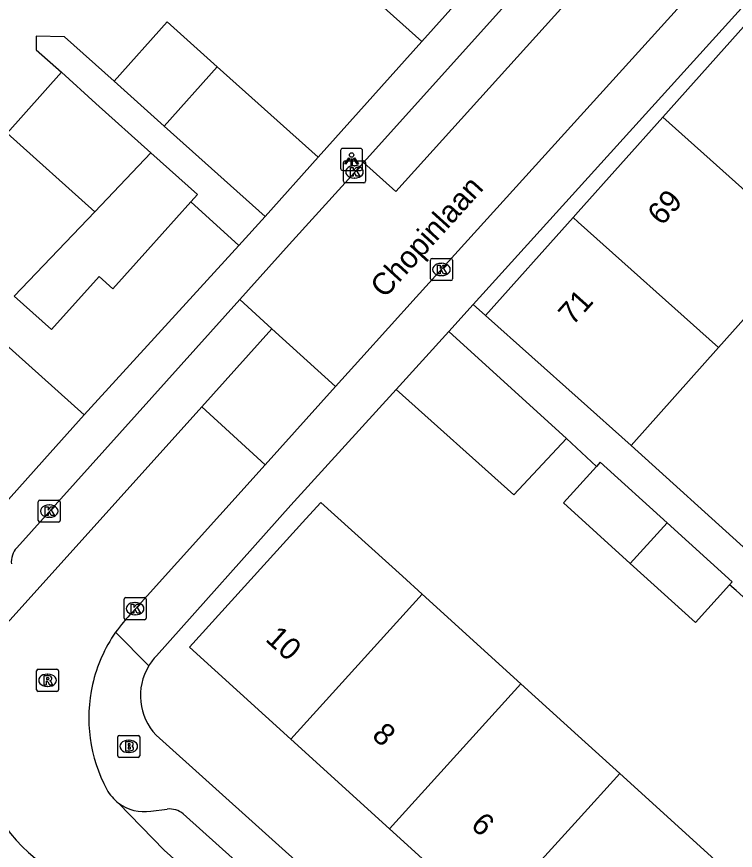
# Model space of a CAD drawing. Extents: x 159040 to 160094, y 381214 to 382518.
# Drawn here: x 159474.48 to 159507.14, y 381732.23 to 381770.11 of the extents above; entities that cross this region are included whole.
import ezdxf

# ---------------------------------------------------------------- set-up
doc = ezdxf.new("R2010")
doc.units = 0
for name, color, linetype in [('IMGEO_Brandkraan', 7, 'Continuous'), ('IMGEO_Kolk', 7, 'Continuous'), ('IMGEO_Lichtpunt', 7, 'Continuous'), ('IMGEO_Muur', 7, 'Continuous'), ('IMGEO_Openbare_ruimte_label', 7, 'Continuous'), ('IMGEO_Pand', 7, 'Continuous'), ('IMGEO_Pand_nummerreeks', 7, 'Continuous'), ('IMGEO_Parkeervlak_open', 7, 'Continuous'), ('IMGEO_Rijbaan_lokaal_open', 7, 'Continuous'), ('IMGEO_Rioolput', 7, 'Continuous'), ('IMGEO_Voetpad_open', 7, 'Continuous')]:
    doc.layers.add(name, color=color, linetype=linetype)

msp = doc.modelspace()

# ---------------------------------------------------------------- linework, layer by layer
at = {"layer": 'IMGEO_Brandkraan'}
for p, q in [((159479.08, 381736.53), (159479.08, 381737.382)), ((159479.155, 381737.456), (159480.007, 381737.456)), ((159480.081, 381737.382), (159480.081, 381736.53)), ((159479.568, 381737.236), (159479.593, 381737.236)), ((159479.591, 381736.676), (159479.566, 381736.676)), ((159480.007, 381736.456), (159479.155, 381736.456))]:
    msp.add_line(p, q, dxfattribs=at)
for points in [[(159479.08, 381736.53), (159479.08, 381737.382)], [(159479.155, 381737.456), (159480.007, 381737.456)], [(159480.081, 381737.382), (159480.081, 381736.53)], [(159479.428, 381737.156), (159479.428, 381736.756), (159479.641, 381736.756)], [(159479.659, 381737.156), (159479.428, 381737.156)], [(159479.607, 381737.075), (159479.553, 381737.075), (159479.553, 381736.999)], [(159479.553, 381736.999), (159479.606, 381736.999)], [(159479.615, 381736.923), (159479.553, 381736.923), (159479.553, 381736.842)], [(159479.553, 381736.842), (159479.615, 381736.842)], [(159480.007, 381736.456), (159479.155, 381736.456)]]:
    msp.add_lwpolyline(points, dxfattribs=at)
for centre, radius, start, end in [((159479.157, 381737.38), 0.0765, 91.552, 178.448), ((159479.157, 381737.38), 0.0765, 91.552, 178.448), ((159480.005, 381737.38), 0.0765, 1.552, 88.448), ((159480.005, 381737.38), 0.0765, 1.552, 88.448), ((159479.608, 381737.037), 0.0379, 267.8285, 90.9355), ((159479.663, 381737.011), 0.145, 59.4692, 91.5367), ((159479.688, 381737.058), 0.0922, 285.5137, 58.1501), ((159479.693, 381736.866), 0.105, 301.3115, 78.989), ((159479.616, 381736.882), 0.0404, 269.8759, 90.5077), ((159479.647, 381737.007), 0.251, 268.6676, 293.5347), ((159479.157, 381736.532), 0.0765, 181.552, 268.448), ((159479.157, 381736.532), 0.0765, 181.552, 268.448), ((159480.005, 381736.532), 0.0765, 271.552, 358.448), ((159480.005, 381736.532), 0.0765, 271.552, 358.448)]:
    msp.add_arc(centre, radius, start, end, dxfattribs=at)
for centre, major_axis, ratio, start_param, end_param in [((159479.567, 381736.956), (-0.387, 0.002), 0.722429, 4.712389, 7.853982), ((159479.592, 381736.956), (-0.39, 0.002), 0.717154, 1.570796, 4.712389)]:
    msp.add_ellipse(centre, major_axis=major_axis, ratio=ratio, start_param=start_param, end_param=end_param, dxfattribs=at)
at = {"layer": 'IMGEO_Kolk'}
for p, q in [((159489.336, 381762.629), (159489.336, 381763.481)), ((159489.411, 381763.555), (159490.263, 381763.555)), ((159490.337, 381763.481), (159490.337, 381762.629)), ((159489.824, 381763.335), (159489.849, 381763.335)), ((159489.847, 381762.775), (159489.822, 381762.775)), ((159490.263, 381762.555), (159489.411, 381762.555)), ((159493.289, 381758.196), (159493.289, 381759.048)), ((159493.364, 381759.122), (159494.216, 381759.122)), ((159494.29, 381759.048), (159494.29, 381758.196)), ((159493.777, 381758.902), (159493.802, 381758.902)), ((159493.8, 381758.342), (159493.775, 381758.342)), ((159494.216, 381758.122), (159493.364, 381758.122)), ((159475.466, 381747.217), (159475.466, 381748.069)), ((159475.541, 381748.143), (159476.393, 381748.143)), ((159475.954, 381747.923), (159475.979, 381747.923)), ((159476.467, 381748.069), (159476.467, 381747.217)), ((159475.977, 381747.363), (159475.952, 381747.363)), ((159476.393, 381747.143), (159475.541, 381747.143)), ((159479.368, 381742.786), (159479.368, 381743.638)), ((159479.443, 381743.712), (159480.295, 381743.712)), ((159479.856, 381743.492), (159479.881, 381743.492)), ((159480.369, 381743.638), (159480.369, 381742.786)), ((159480.295, 381742.712), (159479.443, 381742.712)), ((159479.879, 381742.932), (159479.854, 381742.932))]:
    msp.add_line(p, q, dxfattribs=at)
for points in [[(159489.336, 381762.629), (159489.336, 381763.481)], [(159489.411, 381763.555), (159490.263, 381763.555)], [(159490.337, 381763.481), (159490.337, 381762.629)], [(159489.657, 381763.255), (159489.78, 381763.255), (159489.78, 381763.104), (159489.91, 381763.255), (159490.074, 381763.255), (159489.928, 381763.104), (159490.081, 381762.855), (159489.929, 381762.855), (159489.844, 381763.019), (159489.78, 381762.952), (159489.78, 381762.855), (159489.657, 381762.855), (159489.657, 381763.255)], [(159490.263, 381762.555), (159489.411, 381762.555)], [(159493.289, 381758.196), (159493.289, 381759.048)], [(159493.364, 381759.122), (159494.216, 381759.122)], [(159494.29, 381759.048), (159494.29, 381758.196)], [(159493.61, 381758.822), (159493.733, 381758.822), (159493.733, 381758.671), (159493.863, 381758.822), (159494.027, 381758.822), (159493.881, 381758.671), (159494.034, 381758.422), (159493.882, 381758.422), (159493.797, 381758.586), (159493.733, 381758.519), (159493.733, 381758.422), (159493.61, 381758.422), (159493.61, 381758.822)], [(159494.216, 381758.122), (159493.364, 381758.122)], [(159475.466, 381747.217), (159475.466, 381748.069)], [(159475.541, 381748.143), (159476.393, 381748.143)], [(159476.467, 381748.069), (159476.467, 381747.217)], [(159475.787, 381747.843), (159475.91, 381747.843), (159475.91, 381747.692), (159476.04, 381747.843), (159476.204, 381747.843), (159476.058, 381747.692), (159476.211, 381747.443), (159476.059, 381747.443), (159475.974, 381747.607), (159475.91, 381747.54), (159475.91, 381747.443), (159475.787, 381747.443), (159475.787, 381747.843)], [(159476.393, 381747.143), (159475.541, 381747.143)], [(159479.368, 381742.786), (159479.368, 381743.638)], [(159479.443, 381743.712), (159480.295, 381743.712)], [(159479.689, 381743.412), (159479.812, 381743.412), (159479.812, 381743.261), (159479.942, 381743.412), (159480.106, 381743.412), (159479.96, 381743.261), (159480.113, 381743.012), (159479.961, 381743.012), (159479.876, 381743.176), (159479.812, 381743.109), (159479.812, 381743.012), (159479.689, 381743.012), (159479.689, 381743.412)], [(159480.369, 381743.638), (159480.369, 381742.786)], [(159480.295, 381742.712), (159479.443, 381742.712)]]:
    msp.add_lwpolyline(points, dxfattribs=at)
for centre, start, end in [((159489.413, 381763.479), 91.552, 178.448), ((159489.413, 381763.479), 91.552, 178.448), ((159490.261, 381763.479), 1.552, 88.448), ((159490.261, 381763.479), 1.552, 88.448), ((159489.413, 381762.631), 181.552, 268.448), ((159489.413, 381762.631), 181.552, 268.448), ((159490.261, 381762.631), 271.552, 358.448), ((159490.261, 381762.631), 271.552, 358.448), ((159493.366, 381759.046), 91.552, 178.448), ((159493.366, 381759.046), 91.552, 178.448), ((159494.214, 381759.046), 1.552, 88.448), ((159494.214, 381759.046), 1.552, 88.448), ((159493.366, 381758.198), 181.552, 268.448), ((159493.366, 381758.198), 181.552, 268.448), ((159494.214, 381758.198), 271.552, 358.448), ((159494.214, 381758.198), 271.552, 358.448), ((159475.543, 381748.067), 91.552, 178.448), ((159475.543, 381748.067), 91.552, 178.448), ((159476.391, 381748.067), 1.552, 88.448), ((159476.391, 381748.067), 1.552, 88.448), ((159475.543, 381747.219), 181.552, 268.448), ((159475.543, 381747.219), 181.552, 268.448), ((159476.391, 381747.219), 271.552, 358.448), ((159476.391, 381747.219), 271.552, 358.448), ((159479.445, 381743.636), 91.552, 178.448), ((159479.445, 381743.636), 91.552, 178.448), ((159480.293, 381743.636), 1.552, 88.448), ((159480.293, 381743.636), 1.552, 88.448), ((159479.445, 381742.788), 181.552, 268.448), ((159479.445, 381742.788), 181.552, 268.448), ((159480.293, 381742.788), 271.552, 358.448), ((159480.293, 381742.788), 271.552, 358.448)]:
    msp.add_arc(centre, 0.0765, start, end, dxfattribs=at)
for centre, major_axis, ratio, start_param, end_param in [((159489.823, 381763.055), (-0.387, 0.002), 0.722429, 4.712389, 7.853982), ((159489.848, 381763.055), (-0.39, 0.002), 0.717154, 1.570796, 4.712389), ((159493.776, 381758.622), (-0.387, 0.002), 0.722429, 4.712389, 7.853982), ((159493.801, 381758.622), (-0.39, 0.002), 0.717154, 1.570796, 4.712389), ((159475.953, 381747.643), (-0.387, 0.002), 0.722429, 4.712389, 7.853982), ((159475.978, 381747.643), (-0.39, 0.002), 0.717154, 1.570796, 4.712389), ((159479.855, 381743.212), (-0.387, 0.002), 0.722429, 4.712389, 7.853982), ((159479.88, 381743.212), (-0.39, 0.002), 0.717154, 1.570796, 4.712389)]:
    msp.add_ellipse(centre, major_axis=major_axis, ratio=ratio, start_param=start_param, end_param=end_param, dxfattribs=at)
at = {"layer": 'IMGEO_Lichtpunt'}
for p, q in [((159489.207, 381764.026), (159489.207, 381763.219)), ((159489.207, 381764.026), (159489.207, 381763.219)), ((159490.109, 381764.121), (159489.301, 381764.121)), ((159490.109, 381764.121), (159489.301, 381764.121)), ((159490.203, 381763.219), (159490.203, 381764.026)), ((159490.203, 381763.219), (159490.203, 381764.026)), ((159489.301, 381763.125), (159490.109, 381763.125)), ((159489.301, 381763.125), (159490.109, 381763.125))]:
    msp.add_line(p, q, dxfattribs=at)
for points in [[(159489.581, 381763.69), (159489.62, 381763.662), (159489.432, 381763.4), (159489.394, 381763.427), (159489.581, 381763.69)], [(159489.683, 381763.642), (159489.73, 381763.642), (159489.73, 381763.32), (159489.683, 381763.32), (159489.683, 381763.642)], [(159489.793, 381763.662), (159489.831, 381763.689), (159490.018, 381763.427), (159489.979, 381763.399), (159489.793, 381763.662)]]:
    msp.add_lwpolyline(points, dxfattribs=at)
msp.add_circle((159489.706, 381763.824), 0.0994, dxfattribs=at)
for centre, start, end in [((159489.301, 381764.026), 90, 180), ((159489.301, 381764.026), 90, 180), ((159490.109, 381764.026), 0, 90), ((159490.109, 381764.026), 0, 90), ((159489.301, 381763.219), 180, 270), ((159489.301, 381763.219), 180, 270), ((159490.109, 381763.219), 270, 0), ((159490.109, 381763.219), 270, 360)]:
    msp.add_arc(centre, 0.0946, start, end, dxfattribs=at)
at = {"layer": 'IMGEO_Muur'}
for points in [[(159488.189, 381763.723), (159492.904, 381768.986)], [(159486.95, 381747.912), (159491.728, 381753.174)]]:
    msp.add_lwpolyline(points, dxfattribs=at)
at = {"layer": 'IMGEO_Pand'}
for points in [[(159497.93, 381774.598), (159492.904, 381768.986)], [(159492.904, 381768.986), (159488.306, 381773.102)], [(159503.851, 381765.543), (159508.032, 381770.22)], [(159478.915, 381767.175), (159481.327, 381769.868), (159483.597, 381767.836)], [(159483.597, 381767.836), (159481.187, 381765.141)], [(159483.597, 381767.836), (159488.189, 381763.723)], [(159476.528, 381767.582), (159474.049, 381764.813), (159478.034, 381761.247)], [(159480.589, 381763.924), (159478.083, 381766.168), (159476.528, 381767.582)], [(159481.187, 381765.141), (159478.915, 381767.175)], [(159499.772, 381760.98), (159500, 381761.235), (159503.851, 381765.543)], [(159510.459, 381759.635), (159503.851, 381765.543)], [(159485.777, 381761.03), (159481.187, 381765.141)], [(159478.034, 381761.247), (159480.589, 381763.924)], [(159480.589, 381763.924), (159482.699, 381762.035), (159482.399, 381761.7)], [(159488.189, 381763.723), (159485.777, 381761.03)], [(159482.399, 381761.7), (159480.443, 381759.515), (159478.854, 381757.74), (159478.228, 381758.3), (159476.074, 381755.893), (159474.376, 381757.414), (159478.034, 381761.247)], [(159495.792, 381756.528), (159499.772, 381760.98)], [(159499.772, 381760.98), (159500, 381760.777), (159506.379, 381755.073)], [(159510.459, 381759.635), (159506.379, 381755.073)], [(159502.403, 381750.627), (159500, 381752.772), (159495.792, 381756.528)], [(159473.104, 381756.008), (159477.556, 381752.021)], [(159491.728, 381753.174), (159494.123, 381755.811)], [(159494.123, 381755.811), (159499.476, 381750.946)], [(159506.379, 381755.073), (159502.403, 381750.627)], [(159499.476, 381750.946), (159497.085, 381748.384), (159491.728, 381753.174)], [(159477.556, 381752.021), (159475.747, 381750), (159472.466, 381746.336)], [(159504.041, 381747.106), (159501.005, 381749.861), (159500.832, 381749.671)], [(159502.372, 381745.267), (159499.336, 381748.022), (159500.832, 381749.671)], [(159486.938, 381737.289), (159482.343, 381741.462), (159487.631, 381747.293), (159488.31, 381748.041), (159492.014, 381744.682), (159492.91, 381743.865)], [(159504.041, 381747.106), (159503.89, 381746.94), (159502.372, 381745.267)], [(159506.883, 381744.297), (159506.998, 381744.424), (159504.041, 381747.106)], [(159506.883, 381744.297), (159505.329, 381742.584), (159502.372, 381745.267)], [(159486.938, 381737.289), (159492.91, 381743.865)], [(159492.91, 381743.865), (159497.399, 381739.792)], [(159491.425, 381733.214), (159497.399, 381739.792)], [(159497.399, 381739.792), (159500, 381737.435), (159501.89, 381735.72)], [(159491.425, 381733.214), (159486.938, 381737.289)], [(159501.89, 381735.72), (159500, 381733.639), (159495.913, 381729.138)], [(159501.89, 381735.72), (159506.379, 381731.646)], [(159495.913, 381729.138), (159491.425, 381733.214)]]:
    msp.add_lwpolyline(points, dxfattribs=at)
at = {"layer": 'IMGEO_Parkeervlak_open'}
for points in [[(159495.232, 381757.035), (159507.563, 381770.646)], [(159491.728, 381753.174), (159486.95, 381747.912), (159480.833, 381741.064)], [(159478.982, 381742.137), (159480.487, 381740.611)], [(159480.82, 381737.463), (159502.646, 381717.838), (159502.874, 381717.633)], [(159480.582, 381734.009), (159481.328, 381734.104)], [(159482.048, 381733.888), (159499.447, 381718.275)]]:
    msp.add_lwpolyline(points, dxfattribs=at)
for centre, radius, start, end in [((159482.763, 381739.231), 2.662, 136.4807, 148.7743), ((159482.726, 381739.256), 2.617, 148.8194, 223.2573), ((159480.289, 381735.936), 1.949, 233.0174, 278.6527), ((159481.441, 381733.171), 0.94, 49.7222, 96.8793)]:
    msp.add_arc(centre, radius, start, end, dxfattribs=at)
at = {"layer": 'IMGEO_Rijbaan_lokaal_open'}
for points in [[(159502.12, 381776.684), (159503.595, 381775.326), (159491.718, 381762.164), (159490.252, 381763.489)], [(159505.968, 381772.09), (159492.635, 381757.366), (159490.12, 381754.579), (159488.97, 381753.299)], [(159484.621, 381757.257), (159486.874, 381759.764), (159489.416, 381762.559), (159490.252, 381763.489)], [(159484.621, 381757.257), (159486.087, 381755.923)], [(159482.892, 381752.378), (159486.087, 381755.923)], [(159486.087, 381755.923), (159488.97, 381753.299)], [(159488.97, 381753.299), (159485.771, 381749.749)], [(159482.892, 381752.378), (159473.916, 381742.401)], [(159485.771, 381749.749), (159482.892, 381752.378)], [(159485.771, 381749.749), (159479.731, 381743.038)], [(159499.447, 381718.275), (159498.273, 381716.951), (159481.195, 381732.246), (159479.116, 381734.379)]]:
    msp.add_lwpolyline(points, dxfattribs=at)
for centre, radius, start, end in [((159484.513, 381738.301), 6.731, 135.2701, 145.2565), ((159484.548, 381738.255), 6.787, 145.1068, 167.1074), ((159484.577, 381738.242), 6.817, 167.0525, 208.4511), ((159480.192, 381737.887), 7.729, 184.0895, 231.0462), ((159480.281, 381735.927), 1.937, 208.7871, 233.0417)]:
    msp.add_arc(centre, radius, start, end, dxfattribs=at)
at = {"layer": 'IMGEO_Rioolput'}
for p, q in [((159475.386, 381739.53), (159475.386, 381740.382)), ((159475.461, 381740.456), (159476.313, 381740.456)), ((159476.387, 381740.382), (159476.387, 381739.53)), ((159475.874, 381740.236), (159475.899, 381740.236)), ((159475.897, 381739.676), (159475.872, 381739.676)), ((159476.313, 381739.456), (159475.461, 381739.456))]:
    msp.add_line(p, q, dxfattribs=at)
for points in [[(159475.386, 381739.53), (159475.386, 381740.382)], [(159475.461, 381740.456), (159476.313, 381740.456)], [(159476.387, 381740.382), (159476.387, 381739.53)], [(159475.975, 381740.154), (159475.723, 381740.156), (159475.723, 381739.756)], [(159475.901, 381740.075), (159475.847, 381740.075), (159475.847, 381739.994)], [(159475.847, 381739.994), (159475.899, 381739.994)], [(159475.723, 381739.756), (159475.847, 381739.756), (159475.847, 381739.918), (159475.858, 381739.918)], [(159475.905, 381739.889), (159475.976, 381739.756), (159476.116, 381739.756), (159476.051, 381739.882)], [(159476.313, 381739.456), (159475.461, 381739.456)]]:
    msp.add_lwpolyline(points, dxfattribs=at)
for centre, radius, start, end in [((159475.463, 381740.38), 0.0765, 91.552, 178.448), ((159475.463, 381740.38), 0.0765, 91.552, 178.448), ((159476.311, 381740.38), 0.0765, 1.552, 88.448), ((159476.311, 381740.38), 0.0765, 1.552, 88.448), ((159475.883, 381740.183), 0.19, 274.7715, 282.9687), ((159475.907, 381739.979), 0.0964, 77.0061, 93.1865), ((159475.921, 381740.036), 0.0378, 276.6634, 79.6772), ((159475.974, 381740.044), 0.109, 350.3612, 89.416), ((159475.972, 381740.044), 0.112, 277.5842, 350.9817), ((159475.857, 381739.865), 0.0533, 26.0293, 88.6989), ((159475.956, 381739.829), 0.108, 29.5134, 73.7905), ((159475.463, 381739.532), 0.0765, 181.552, 268.448), ((159475.463, 381739.532), 0.0765, 181.552, 268.448), ((159476.311, 381739.532), 0.0765, 271.552, 358.448), ((159476.311, 381739.532), 0.0765, 271.552, 358.448)]:
    msp.add_arc(centre, radius, start, end, dxfattribs=at)
for centre, major_axis, ratio, start_param, end_param in [((159475.873, 381739.956), (-0.387, 0.002), 0.722429, 4.712389, 7.853982), ((159475.898, 381739.956), (-0.39, 0.002), 0.717154, 1.570796, 4.712389)]:
    msp.add_ellipse(centre, major_axis=major_axis, ratio=ratio, start_param=start_param, end_param=end_param, dxfattribs=at)
at = {"layer": 'IMGEO_Voetpad_open'}
for points in [[(159490.252, 381763.489), (159502.12, 381776.684)], [(159478.915, 381767.175), (159476.66, 381769.195), (159475.372, 381769.226), (159475.372, 381768.595), (159476.528, 381767.582)], [(159492.904, 381768.986), (159488.189, 381763.723)], [(159482.399, 381761.7), (159484.576, 381759.714)], [(159485.777, 381761.03), (159484.576, 381759.714)], [(159484.576, 381759.714), (159477.556, 381752.021)], [(159474.485, 381745.981), (159484.621, 381757.257)], [(159494.123, 381755.811), (159495.232, 381757.035)], [(159495.232, 381757.035), (159495.792, 381756.528)], [(159500.832, 381749.671), (159499.476, 381750.946)], [(159502.403, 381750.627), (159507.667, 381745.872)], [(159509.318, 381742.104), (159507.182, 381744.033), (159506.883, 381744.297)]]:
    msp.add_lwpolyline(points, dxfattribs=at)
msp.add_arc((159475.227, 381745.331), 0.987, 138.7512, 185.0331, dxfattribs=at)

# ---------------------------------------------------------------- texts
at = {"layer": 'IMGEO_Openbare_ruimte_label'}
msp.add_text('Chopinlaan', height=1, rotation=47.8381, dxfattribs=at).set_placement((159491.207, 381757.278))
at = {"layer": 'IMGEO_Pand_nummerreeks'}
for s, rotation, p in [('69', 48.2048, (159503.806, 381760.572)), ('71', 48.2039, (159499.753, 381756.037)), ('10', 317.7544, (159485.742, 381741.779)), ('8', 317.7544, (159490.578, 381737.387)), ('6', 317.7544, (159495.07, 381733.308))]:
    msp.add_text(s, height=1, rotation=rotation, dxfattribs=at).set_placement(p)

doc.saveas('drawing.dxf')
